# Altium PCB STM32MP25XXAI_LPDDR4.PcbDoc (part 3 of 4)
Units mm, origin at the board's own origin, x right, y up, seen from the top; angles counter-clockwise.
Board outline 172 x 137 mm, 4 copper layers (Top Layer, Signal Layer 1, Signal Layer 2, Bottom Layer), stack 1.614 mm thick; 188 components, 144 nets, 1216 pads, 838 vias.
Unrouted connection lines stored in the file: 13.
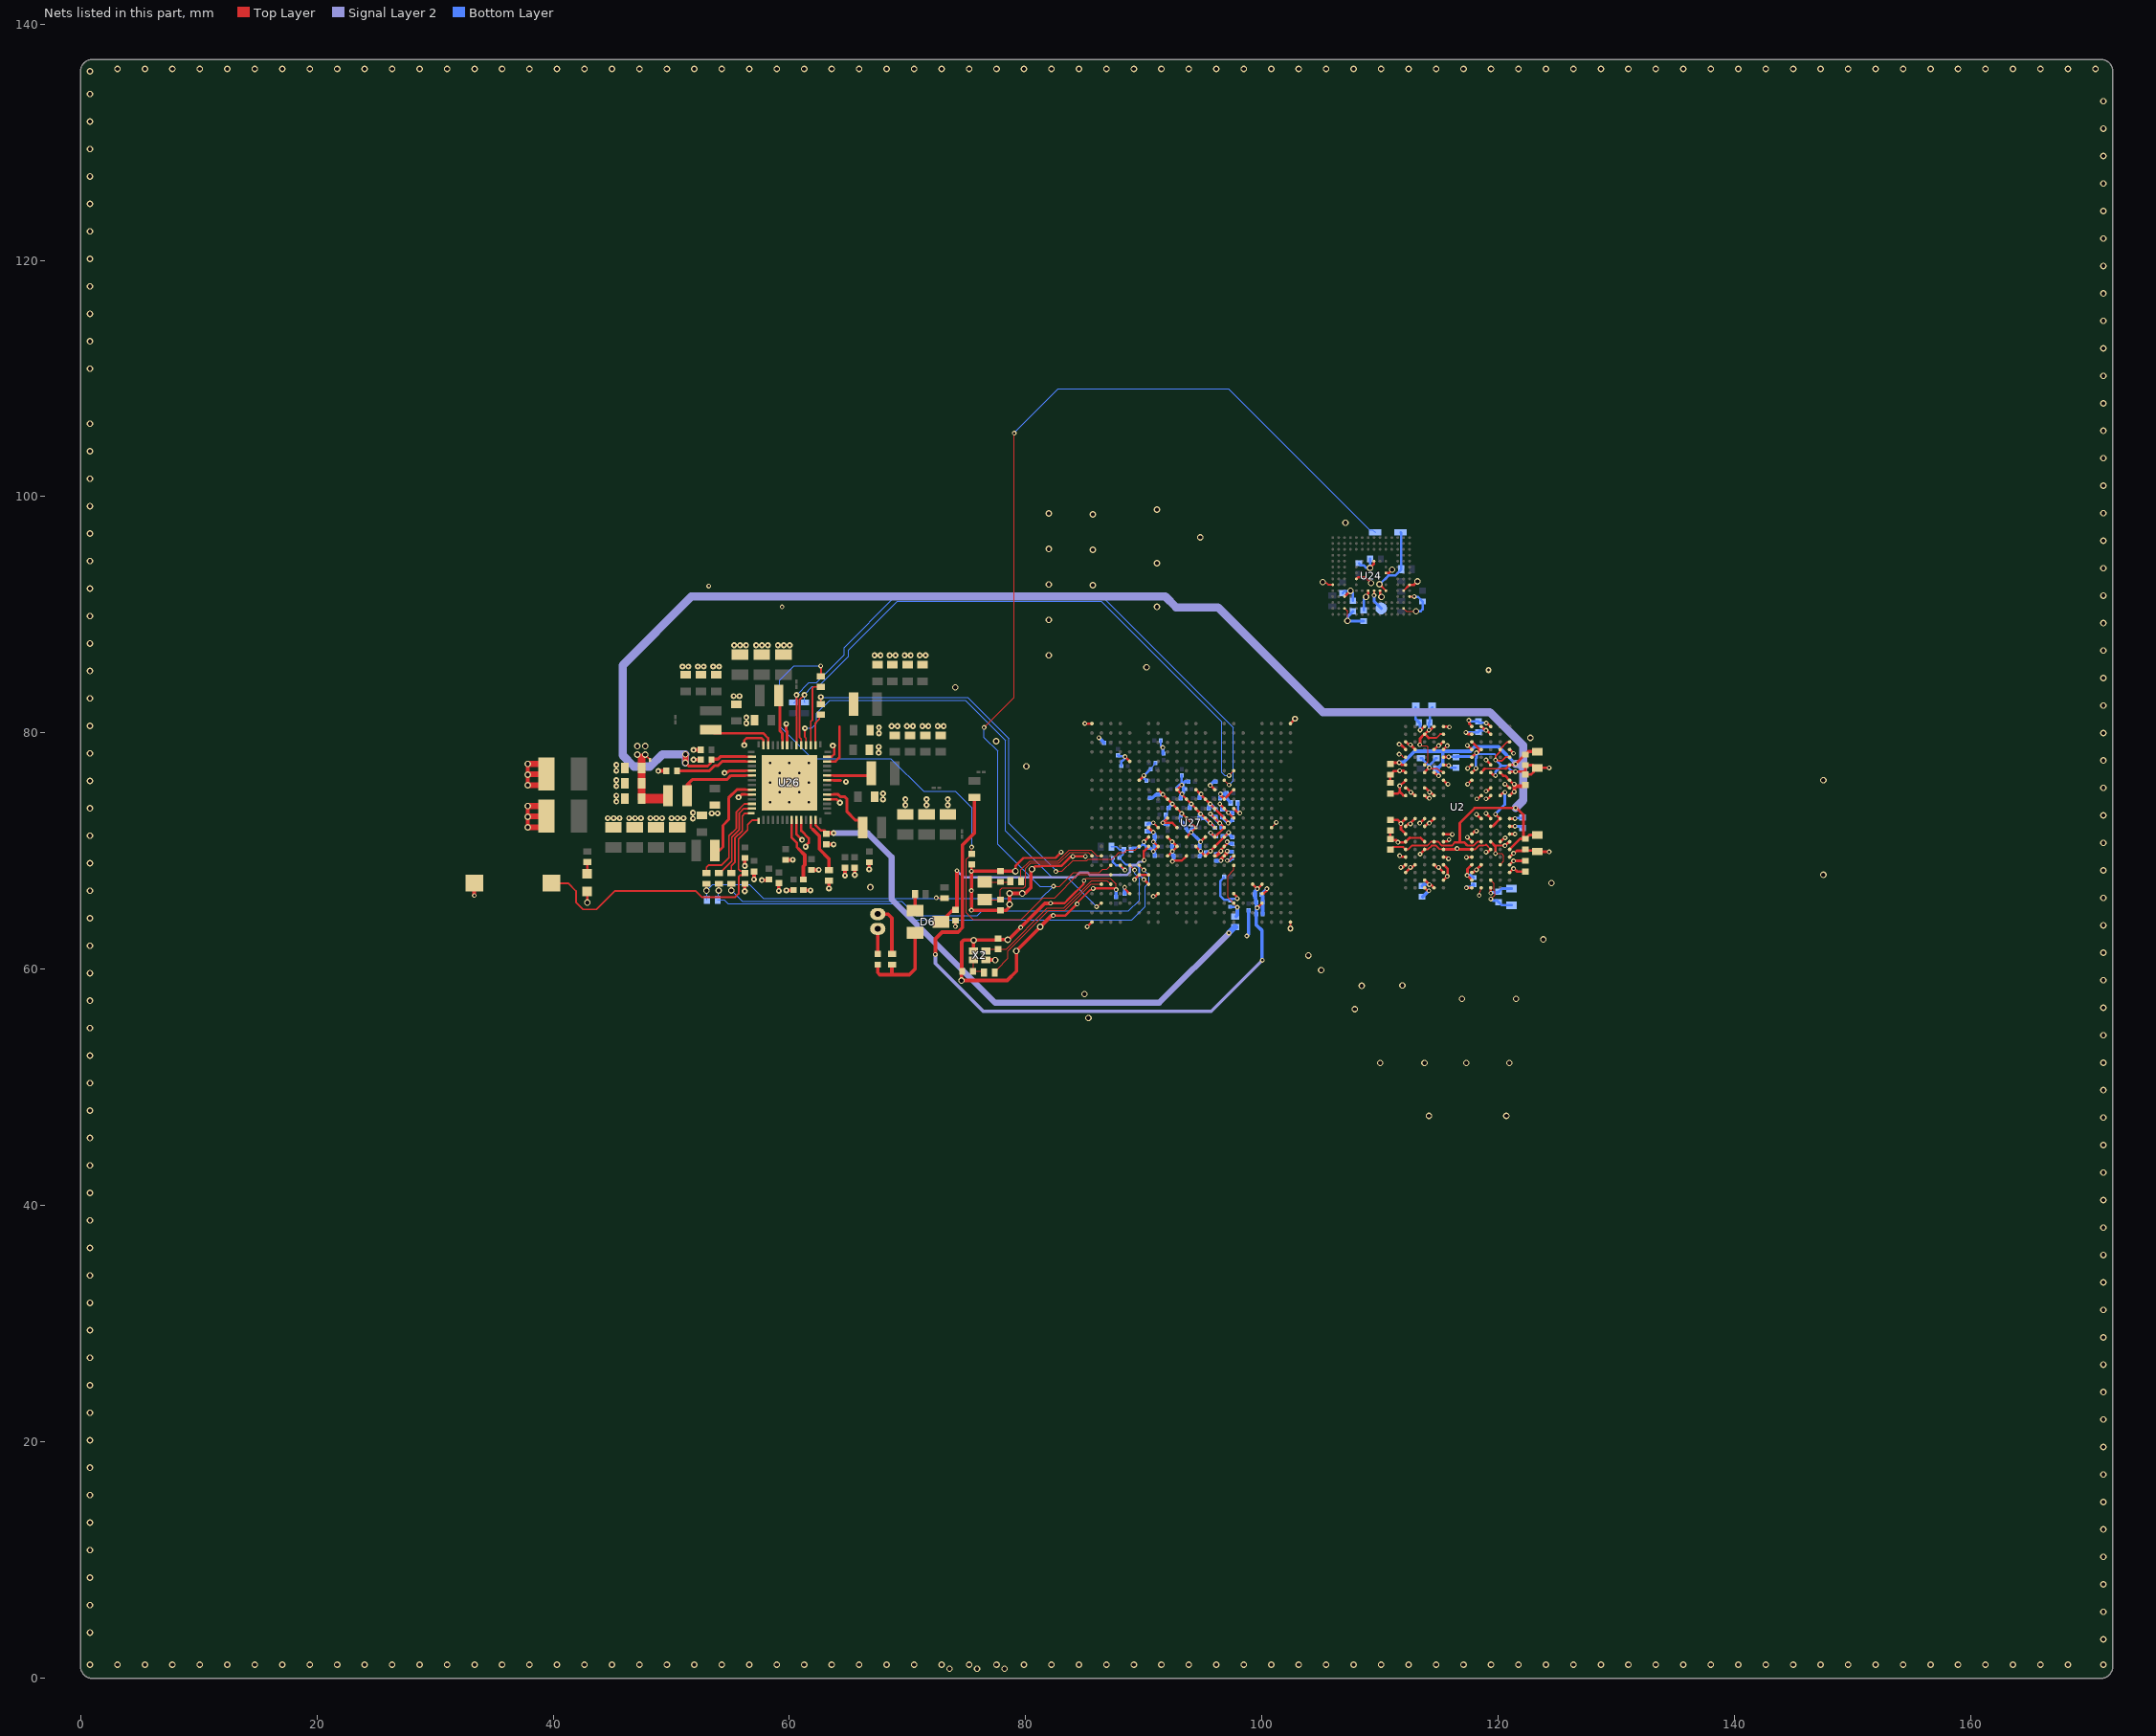
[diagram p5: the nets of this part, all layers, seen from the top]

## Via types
v1: diameter 0.55, hole 0.35, Top Layer to Bottom Layer, 387 vias
v2: diameter 0.4, hole 0.2, Top Layer to Bottom Layer, tented both sides, 173 vias
v3: diameter 0.5, hole 0.2, Top Layer to Bottom Layer, 146 vias
v4: diameter 0.4, hole 0.2, Top Layer to Bottom Layer, 129 vias
v5: diameter 0.5, hole 0.25, Top Layer to Bottom Layer, 3 vias

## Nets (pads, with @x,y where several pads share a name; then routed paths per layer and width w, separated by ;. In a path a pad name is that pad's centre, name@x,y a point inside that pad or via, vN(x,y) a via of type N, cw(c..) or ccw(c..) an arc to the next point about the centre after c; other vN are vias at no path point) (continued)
GND: B2.1 C1.2 C2.1 C3.1 C4.2 C5.1 C6.1 C7.1 C8.1 C9.1 C10.1 C11.2 C12.1 C13.2 C14.1 C15.1 C16.2 C17.1 C18.2 C19.1 C20.1 C21.1 C22.1 C23.1 C24.1 C25.1 C26.1 C27.1 C28.1 C29.1 C30.1 C31.1 C32.1 C33.1 C34.1 C35.1 C36.1 C37.1 C38.1 C39.1 C40.1 C41.1 C42.2 C43.1 C44.2 C45.1 C46.1 C47.2 C50.2 C51.1 C52.1 C53.1 C54.2 C55.1 C56.1 C57.1 C58.1 C59.1 C60.1 C61.1 C62.1 C63.1 C64.1 C65.1 C66.1 C67.1 C68.1 C69.1 C70.1 C71.1 C72.1 C73.1 C74.1 C75.1 C79.1 C81.2 C86.2 C87.1 C89.1 C90.1 C91.2 C92.2 C96.1 C97.1 C98.1 C100.1 C101.1 C102.1 C103.1 C104.1 C105.1 C106.2 C107.2 C108.2 C123.1 C124.2 C125.2 C130.2 C131.1 C141.2 C142.2 C151.2 C152.1 C153.1 C154.1 C155.1 C156.1 C157.1 C175.2 C176.1 C177.1 C178.1 C179.1 C180.1 C181.1 C182.1 C183.1 C184.1 C186.1 C187.1 C188.1 C189.1 C190.2 C193.1 C199.1 C200.1 C202.1 C204.1 C206.1 C207.1 C208.2 C209.1 C212.1 C217.2 C234.1 C275.1 C285.1 LD11.2 R1.1 R57.1 R156.1 U2.A3 U2.A10 U2.AB3 U2.AB5 U2.AB8 U2.AB10 U2.C1 U2.C5 U2.C8 U2.C12 U2.D2 U2.D4 U2.D9 U2.D11 U2.E1 U2.E5 U2.E8 U2.E12 U2.G1 U2.G3 U2.G5 U2.G8 U2.G10 U2.G12 U2.J1 U2.J3 U2.J10 U2.J12 U2.K2 U2.K4 U2.K9 U2.K11 U2.N2 U2.N4 U2.N9 U2.N11 U2.P1 U2.P3 U2.P10 U2.P12 U2.T1 U2.T3 U2.T5 U2.T8 U2.T10 U2.T12 U2.V1 U2.V5 U2.V8 U2.V12 U2.W2 U2.W4 U2.W9 U2.W11 U2.Y1 U2.Y5 U2.Y8 U2.Y12 U24.A6 U24.C4 U24.E7 U24.G5 U24.H10 U24.J5 U24.K8 U24.N2 U24.N5 U24.P4 U24.P6 U26.9 U26.10 U26.18 U26.22 U26.27 U26.36 U26.41 U26.47 U26.52 U26.57 U27.A1 U27.A22 U27.AB1 U27.AB22 U27.E5 U27.G6 U27.H8 U27.H10 U27.H12 U27.H14 U27.H16 U27.J9 U27.J11 U27.J13 U27.J15 U27.K10 U27.K12 U27.K14 U27.L9 U27.L11 U27.L13 U27.L15 U27.M7 U27.M10 U27.M12 U27.M14 U27.M20 U27.N7 U27.N9 U27.N11 U27.N13 U27.N15 U27.P8 U27.P10 U27.P12 U27.P14 U27.R9 U27.R11 U27.R13 U27.R15 U27.T4 U27.U6 U27.U7 U27.W5 U27.W8 U27.W16 U27.W19 X2.2 X2.4 | length 279.9
  Top Layer w0.09: v2(84.925,67.5) 85.12,67.695 87.155,67.695 87.183,67.667 87.65,67.2 v2(87.65,66.75) ; U24.N2@111.98,90.542 112.23,90.292 v1(113.03,90.292) ; U2.T10@113.75,76.65 U2.T10@113.75,76.663 ; v4@114.15,77.063 v4(114.15,77.075) v4@114.228,77.075 ; v4(118.15,73.125) 118.163,73.125 v4@118.175,73.125 ; U2.K4@118.525,72.775 U2.K4@118.55,72.775 ; v4@119.7,69.85 v4(119.75,69.8) 119.755,69.795 120.273,69.795 120.445,69.622 120.445,69.145 U2.D2@120.15,68.85
  Top Layer w0.1: v3@44.624,72.799 v3@44.625,72.8 ; X2.2@75.547,61.575 X2.2@75.548,61.576 ; v1@75.573,62.448 v1(75.587,62.462) v1@75.6,62.475 ; U27.M20@100.8,72 101.2,72.4 v4(101.2,72.425) ; v4(111.6,78.2) 111.658,78.143 111.764,78.143 111.941,77.965 112.135,77.965 U2.V12@112.15,77.95
  Top Layer w0.15: v2(84.345,65.531) 84.345,65.598 84.448,65.702 84.448,65.708 85.465,66.725 85.523,66.725 85.636,66.838 v2(85.703,66.838) ; v1(105.13,92.762) 105.201,92.692 105.466,92.692 105.611,92.547 105.975,92.547 U24.A6@105.98,92.542 ; U24.P4@112.48,91.542 v2(112.88,91.542) ; 112.5,71.125 113.413,71.125 ; v4@114.228,77.075 114.228,77.065 114.318,76.975 114.832,76.975 115.037,76.77 115.19,76.77 115.31,76.65 U2.T8@115.35,76.65 ; 119.7,70.475 v4(120.55,70.475) ; U2.Y1@120.899,79.272 120.853,79.226 120.724,79.226 120.15,78.652 U2.W2@120.15,78.6 120.15,78.43 119.786,78.065 119.786,77.754 119.741,77.709 119.773,77.677 119.978,77.677 120.02,77.635 120.29,77.635 120.611,77.957 120.944,77.957 U2.V1@120.95,77.95
  Top Layer w0.2: v1(42.887,65.648) LD11.2@42.887,66.577 ; U26.27@63.17,78 63.579,78 63.77,78.191 63.77,78.91 v3@63.816,78.956 ; v3(63.67,78.93) v3@63.727,78.873 ; C87.1@74.05,64.125 74.05,63.634 v2(74.051,63.633) ; v2(75.402,68.305) 75.416,68.319 C33.1@75.416,68.915 ; v1(79.125,68.3) 79.125,68.75 79.8,69.425 82.507,69.425 v2(83.002,69.92) ; v1(80.525,68.475) 80.568,68.475 80.818,68.725 81.262,68.725 81.287,68.75 83.012,68.75 83.784,69.522 83.94,69.522 v2(83.978,69.56) v2(85.046,69.56) ; v2(82.1,65.6) 83.28,65.6 83.703,66.023 84.887,67.207 84.887,67.462 v2(84.925,67.5) ; v2(82.325,64.55) 83.364,64.55 v2(84.345,65.531) ; v2(85,80.805) 85.005,80.8 U27.A1@85.6,80.8 ; v2(85.2,63.6) U27.AB1@85.6,64 ; v2(85.703,66.838) 87.508,66.838 87.596,66.75 v2(87.65,66.75) ; U27.T4@88,68.8 v2(88.4,68.4) ; v2(88.37,66.944) 88.408,66.905 88.408,66.792 U27.W5@88.8,66.4 ; v2(88.4,78) U27.E5@88.8,77.6 ; v2(89.2,67.6) U27.U6@89.6,68 U27.U7@90.4,68 ; U27.G6@89.6,76 v2(90,76.4) ; v2(90,70.8) U27.N7@90.4,71.2 ; v2(90.788,66.173) 90.827,66.211 90.984,66.211 91.173,66.4 U27.W8@91.2,66.4 ; v2@90.8,70 U27.P8@91.2,70.4 v2(90.8,70.8) ; U27.H8@91.2,75.2 v2(91.6,74.8) U27.J9@92,74.4 v2(92.4,74) v2@93.225,73.175 ; U27.R9@92,69.6 92.025,69.6 v2(92.4,69.975) 92.8,70.375 U27.P10@92.8,70.4 92.4,70.8 U27.N9@92,71.2 ; U27.L9@92,72.8 v2(91.6,72.4) 92.4,72.4 U27.M10@92.8,72 ; v2@92.454,69.1 92.4,69.1 92.5,69.2 93.2,69.2 U27.R11@93.6,69.6 ; v2(93.2,73.175) v2@93.225,73.175 ; v2(93.201,75.6) 92.801,75.2 v2@93.226,74.775 ; v2(93.226,74.85) v2@93.226,74.775 ; U27.N11@93.6,71.2 v2(94,71.6) U27.M12@94.4,72 v2@93.225,73.175 ; U27.P12@94.4,70.4 v2(94.8,70) U27.R13@95.2,69.6 95.787,70.188 ; U27.H12@94.407,75.2 94.757,74.85 v2(94.832,74.85) 94.832,74.775 v2(95.607,74) U27.L15@96.807,72.8 ; v2(94.8,70.8) U27.N13@95.2,71.2 ; v2@95.625,75.575 U27.H14@96,75.2 ; U27.P14@96,70.4 95.787,70.188 ; U27.M14@96,72 95.626,72.375 94.851,73.15 v2(94.801,73.15) 94.801,73.2 v2(94.001,74) v2@93.226,74.775 ; v2(96.475,74.85) 96.514,74.812 96.514,74.686 U27.J15@96.8,74.4 U27.H16@97.6,75.2 ; U27.L15@96.8,72.8 97.087,72.513 97.087,72.413 v2(97.125,72.375) ; v2(97.175,71.575) 95.787,70.188 ; U27.W16@97.6,66.4 97.862,66.138 97.862,66.038 v2(97.9,66) ; U27.W19@100,66.4 100.019,66.419 100.144,66.419 v4@100.4,66.675 ; v5(102.4,63.45) U27.AB22@102.4,64 ; U27.A22@102.41,80.8 102.41,80.811 102.76,81.161 v5@102.76,81.175 ; U24.C4@106.98,91.542 107.43,91.992 107.44,91.992 v1(107.48,92.032) ; U24.E7@107.98,93.042 108.13,93.192 108.725,93.192 v1(109.23,92.687) ; v1(108.805,91.517) 108.805,91.605 108.98,91.78 U24.G5@108.98,92.042 ; v1(109.13,93.967) 109.48,94.317 U24.H10@109.48,94.542 ; U24.J5@109.98,92.042 109.98,91.737 110.105,91.612 v1(110.105,91.517) ; U24.K8@110.48,93.542 110.73,93.542 v1(111.005,93.817) ; U24.N5@111.98,92.042 U24.P6@112.48,92.542 112.86,92.542 v1(113.155,92.837)
  Top Layer w0.21: v3(56.175,78.975) 56.175,79.375 56.38,79.58 57.609,79.58 57.8,79.389 U26.41@57.8,78.97 ; 56.275,74.8 U26.52@56.83,74.8 ; 56.275,76.8 U26.47@56.83,76.8 ; U26.36@59.8,78.97 59.8,79.525 ; U26.9@60.6,72.63 60.6,71.42 v3(61.068,70.952) ; U26.10@61,72.63 61,71.734 61.635,71.099 61.635,70.72 61.37,70.456 v3(61.37,70.377) ; U26.18@63.17,74.4 63.972,74.4 v3(64.272,74.1) ; U26.22@63.17,76 63.725,76
  Top Layer w0.22: C50.2@110.85,71.75 C102.1@110.85,71.025 110.931,70.944 111.331,70.944 111.526,70.75 v2@111.55,70.75 ; C105.1@110.85,75.775 C101.1@110.85,76.475 110.875,76.475 111.02,76.62 111.02,76.637 111.149,76.766 v4@111.65,76.766 ; v2@111.55,70.747 112.076,70.747 112.129,70.8 U2.G12@112.15,70.8 112.172,70.8 112.497,71.125 112.5,71.125 ; v4(111.65,69.625) 111.699,69.625 111.809,69.515 112.135,69.515 U2.E12@112.15,69.5 ; v4(111.65,76.8) 111.661,76.79 111.989,76.79 112.129,76.65 U2.T12@112.15,76.65 ; U2.C12@112.15,68.2 112.172,68.2 112.497,68.525 112.525,68.525 112.56,68.559 112.638,68.559 112.929,68.85 U2.D11@112.95,68.85 ; U2.J12@112.15,72.1 112.172,72.1 112.413,72.341 112.516,72.341 112.55,72.375 112.563,72.375 112.938,72.75 U2.K11@112.95,72.75 ; U2.P12@112.15,75.35 112.166,75.335 112.244,75.335 112.579,75 v4@112.6,75 ; U2.Y12@112.15,79.25 112.172,79.25 112.388,79.034 112.516,79.034 v4(112.55,79) U2.W11@112.95,78.6 ; v4@112.585,74.991 112.638,74.991 112.929,74.7 U2.N11@112.95,74.7 ; v4(113.375,80.25) 113.424,80.25 113.509,80.334 113.513,80.334 113.729,80.55 U2.AB10@113.75,80.55 ; 113.413,71.125 113.738,70.8 U2.G10@113.75,70.8 ; U2.A10@113.75,66.9 113.772,66.9 113.988,66.684 114.091,66.684 v4(114.125,66.65) ; U2.J10@113.75,72.1 113.772,72.1 114.013,72.341 114.116,72.341 v4(114.15,72.375) 114.163,72.375 114.538,72.75 U2.K9@114.55,72.75 ; U2.P10@113.75,75.35 113.766,75.335 113.849,75.335 114.133,75.05 114.175,75.05 114.188,75.05 114.538,74.7 U2.N9@114.55,74.7 ; U2.T10@113.75,76.663 v4@114.15,77.063 ; U2.D9@114.55,68.85 114.572,68.85 114.763,68.659 114.916,68.659 v4(114.95,68.625) 114.95,68.613 115.35,68.213 U2.C8@115.35,68.2 ; U2.W9@114.55,78.6 114.572,78.6 114.863,78.891 114.916,78.891 v4(114.95,78.925) 114.985,78.959 115.038,78.959 115.329,79.25 U2.Y8@115.35,79.25 ; U2.E8@115.35,69.5 115.366,69.485 115.592,69.485 115.727,69.35 v4(115.775,69.35) ; U2.G8@115.35,70.8 115.366,70.815 115.692,70.815 115.777,70.9 v4@115.825,70.9 ; U2.V8@115.35,77.95 115.363,77.963 115.788,77.963 v4(115.8,77.975) ; U2.AB8@115.35,80.55 115.366,80.535 115.767,80.535 115.802,80.5 v4(115.85,80.5) ; v4(117.3,69.475) 117.313,69.488 117.738,69.488 U2.E5@117.75,69.5 ; v4(117.375,71.175) U2.G5@117.738,70.813 ; v4(117.5,81.075) 117.535,81.041 117.535,80.787 117.75,80.572 U2.AB5@117.75,80.55 ; U2.C5@117.75,68.2 117.877,68.2 118.102,68.425 v4(118.15,68.425) 118.15,68.438 118.55,68.838 U2.D4@118.55,68.85 ; U2.T5@117.75,76.65 v4(118.1,77) ; U2.V5@117.75,77.95 117.763,77.95 118.138,78.325 v4(118.15,78.325) 118.185,78.359 118.288,78.359 U2.W4@118.529,78.6 ; U2.Y5@117.75,79.25 118.385,78.615 118.513,78.615 U2.W4@118.529,78.6 ; v4@118.163,73.125 118.538,72.75 U2.K4@118.55,72.75 ; v4(118.175,74.425) 118.21,74.459 118.288,74.459 118.529,74.7 U2.N4@118.55,74.7 ; U2.W4@118.55,78.6 U2.W4@118.529,78.6 ; v4(118.95,75.075) 118.999,75.075 119.089,75.165 119.128,75.165 119.273,75.31 119.289,75.31 119.329,75.35 U2.P3@119.35,75.35 ; v4(118.97,80.845) 118.97,80.84 118.98,80.83 118.95,80.8 118.985,80.766 119.113,80.766 119.329,80.55 U2.AB3@119.35,80.55 ; v4(119.35,66.45) U2.A3@119.35,66.9 ; U2.G3@119.35,70.8 119.75,70.4 v4(119.75,69.8) ; U2.J3@119.35,72.1 119.366,72.115 119.516,72.115 U2.K2@120.15,72.75 120.138,72.75 119.763,73.125 v4(119.75,73.125) ; U2.T3@119.35,76.65 119.566,76.434 v4@119.716,76.434 ; U2.N2@120.15,74.7 120.391,74.941 120.516,74.941 v4(120.55,74.975) ; v4(120.55,70.475) 120.585,70.509 120.638,70.509 120.929,70.8 U2.G1@120.95,70.8 ; v4(120.55,75.675) 120.625,75.675 U2.P1@120.95,75.35 ; U2.C1@120.95,68.2 v4(121.275,68.525) 121.324,68.525 121.574,68.275 C106.2@122.25,68.275 ; U2.E1@120.95,69.5 120.963,69.5 121.263,69.8 121.324,69.8 121.549,70.025 C103.1@122.25,70.025 ; U2.J1@120.95,72.1 v4(121.4,72.1) ; U2.T1@120.95,76.65 120.972,76.65 121.047,76.725 v4(121.45,76.725) C107.2@122.275,76.725 ; C103.1@122.25,70.15 122.338,70.063 123.188,70.063 C51.1@123.275,69.975 ; C51.1@123.3,69.975 123.325,69.95 v4(124.3,69.95) ; C100.1@123.3,77.025 C100.1@123.175,77.025 ; v4(124.3,77.05) 123.2,77.05 C100.1@123.175,77.025 ; C107.2@122.275,76.725 C104.1@122.275,77.275 122.925,77.275 C100.1@123.175,77.025 ; C107.2@122.275,76.725 C107.2@122.275,76.5 122.775,76.5 122.965,76.69 122.965,76.815 C100.1@123.175,77.025
  Top Layer w0.25: v3(54.508,76.625) 54.556,76.673 54.757,76.673 54.884,76.8 56.275,76.8 ; v3(55.687,74.563) 55.721,74.563 55.959,74.8 56.275,74.8 ; v3(59.725,80.775) 59.725,80.214 59.8,80.139 59.8,79.525 ; 63.725,76 64.33,76 ; v3@64.257,74.1 v3(64.272,74.1)
  Top Layer w0.3: v2(33.319,66.245) 33.324,66.25 33.324,67.279 B2.1@33.34,67.295 ; v1(37.848,72.014) v1(37.848,72.914) v1(37.848,73.814) ; v1(37.848,75.576) v1(37.848,76.476) v1(37.848,77.376) ; v3(48.895,76.79) C43.1@49.555,76.79 ; v3(51.885,77.75) C40.1@52.495,77.75 ; v3(51.885,78.575) C39.1@52.495,78.575 ; v3@56.225,68.81 C217.2@56.225,69.42 ; v3@56.227,66.58 C155.1@56.227,67.185 ; v3(57,67.61) C154.1@57,68.215 ; v3(57.665,67.55) C142.2@58.275,67.55 ; v3@59.1,66.69 C141.2@59.1,67.3 ; C153.1@59.675,69.27 v3(60.285,69.27) ; v3(59.74,66.68) C91.2@60.35,66.68 ; C208.2@61.175,66.68 v3(61.785,66.68) ; C209.1@61.85,68.42 v3(62.485,68.42) ; C156.1@63.125,70.57 v3(63.735,70.57) ; v3(63.35,66.84) R57.1@63.35,67.5 ; v3(64.7,67.93) C189.1@64.7,68.59 ; v3(65.525,67.99) C188.1@65.525,68.59 C188.1@65.525,68.65 ; v3@66.75,68.465 66.747,68.467 66.747,69.063 C190.2@66.75,69.065 ; C92.2@74.563,59.875 74.563,59.087 74.588,59.063 78.438,59.063 79.225,59.85 79.225,61.525 v1(79.2,61.55) 81.225,63.575 v1(81.225,63.6) 82.156,64.531 82.306,64.531 v2(82.325,64.55) ; C92.2@74.625,59.825 74.576,59.874 74.576,62.299 74.752,62.475 75.6,62.475 76,62.475 76.013,62.488 76.663,62.488 76.675,62.475 77.5,62.475 77.625,62.6 C90.1@77.65,62.6 77.736,62.514 v1@78.475,62.514 ; v2(75.4,65) C86.2@77.85,65 ; 75.4,65.275 v2@75.4,66.65 ; v2@75.4,68.3 v2@75.402,68.3 ; v2(75.402,66.655) v2@75.402,68.3 ; v2(75.402,68.305) v2@75.402,68.3 ; X2.2@75.573,61.551 v1@75.573,62.448 ; X2.4@76.66,60.788 76.667,60.794 77.408,60.794 v1(77.415,60.788) ; C86.2@77.955,65.105 C86.2@77.85,65 ; v1(78.475,62.5) 78.525,62.5 v2(79.575,63.55) 81.606,65.581 v2@82.081,65.581 ; v1(79.125,68.3) C81.2@77.85,68.3 v2@75.402,68.3 ; v1(80.525,68.475) 80.43,68.38 80.43,66.905 79.993,66.468 79.748,66.468 v1(79.7,66.42) 79.695,66.425 v1(78.625,66.425) v1(78.625,65.5) 78.578,65.452 78.578,65.239 78.339,65 C86.2@77.85,65 ; U27.M7@90.4,72 v2(90.8,71.6) ; v2(96.525,69.2) 96.544,69.219 96.544,69.344 U27.R15@96.8,69.6 96.975,69.775 96.975,69.898 97.05,69.973 v2(97.05,70)
  Top Layer w0.5: v1(37.848,72.014) 39.39,72.014 C18.2@39.437,72.061 ; v1(37.848,72.914) 37.862,72.914 37.909,72.961 C18.2@39.437,72.961 ; v1(37.848,73.814) C18.2@39.379,73.814 ; v1(37.848,75.576) 39.39,75.576 C42.2@39.437,75.623 ; v1(37.848,76.476) 37.862,76.476 37.909,76.523 C42.2@39.437,76.523 ; v1(37.848,77.376) C42.2@39.379,77.376
  Bottom Layer w0.1: C73.1@90.575,76.925 90.7,77.05 90.7,77.13 90.85,77.28 90.85,77.35 C66.1@90.9,77.4 ; C212.1@91.86,73.1 92.032,73.272 92.032,73.582 C3.1@92.1,73.65 ; C10.1@92.35,70.327 C10.1@92.35,70.45
  Bottom Layer w0.15: v4@118.15,78.35 118.191,78.35 118.341,78.2 119.684,78.2 119.75,78.134 v4@119.75,77.75
  Bottom Layer w0.2: C75.1@87.375,69.425 87.375,69.075 87.65,68.8 87.9,68.8 88.3,68.4 v2(88.4,68.4) ; C70.1@87.8,78.1 87.862,78.038 88.362,78.038 v2(88.4,78) 88.405,77.996 88.405,77.854 88.205,77.655 88.18,77.655 88.163,77.655 88.075,77.567 C275.1@88.075,77.2 ; C79.1@88.9,70.125 89.075,70.3 89.625,70.3 89.962,70.636 89.962,70.761 v2(90,70.8) 90.038,70.761 90.038,70.522 C234.1@90.275,70.285 ; v2@89.988,76.388 90.038,76.338 90.038,76.137 C69.1@90.205,75.97 ; v2(90,76.4) 90.525,76.925 C73.1@90.575,76.925 ; C66.1@90.9,77.4 C66.1@90.975,77.475 ; C97.1@91.425,79.375 91.425,78.955 91.6,78.781 v2(91.6,78.775) ; v2(93.201,75.6) C71.1@93.201,76.4 ; C11.2@95.25,69.9 95.312,69.962 95.587,69.962 v2(95.625,70) ; C89.1@96.75,67.8 96.75,67.75 96.45,67.45 96.45,66.225 96.775,65.9 97.3,65.9 97.35,65.95 97.444,65.95 97.456,65.962 97.721,65.962 97.862,65.962 v2(97.9,66) ; C178.1@106.835,91.855 107,92.02 107.5,92.02 107.685,91.835 C182.1@107.685,91.18 ; C177.1@108.19,94.355 108.345,94.2 108.583,94.2 108.783,94.001 109.104,94.001 109.15,93.955 C180.1@109.15,94.739 ; C181.1@108.602,90.38 108.602,91.282 v1@108.825,91.505 ; v2@112.9,91.53 113.19,91.53 C179.1@113.59,91.13 113.59,90.467 113.433,90.31 113.08,90.31 v1@113.05,90.28
  Bottom Layer w0.22: C123.1@113,82.125 113,81.2 ; C123.1@113,82.15 113,81.2 ; C125.2@113.275,80.875 C125.2@113.316,80.834 ; v4(113.375,80.25) C125.2@113.375,80.775 ; v4@113.375,80.275 C125.2@113.375,80.775 ; R156.1@113.425,77.875 113.52,77.875 113.665,77.73 113.665,77.685 114.116,77.234 114.116,77.134 114.15,77.1 114.185,77.134 114.185,77.262 114.185,77.274 114.58,77.67 114.58,77.73 114.725,77.875 C131.1@114.75,77.875 ; C175.2@113.55,66.15 C175.2@113.6,66.15 ; v4@115.8,78 116.35,78 C130.2@116.4,77.95 116.46,78.01 117.86,78.01 117.86,78.035 v4(118.15,78.325) ; v4(117.5,81.075) 117.6,80.975 C124.2@118.3,80.975 118.416,80.859 118.916,80.859 v4@118.95,80.825 ; v4@118.1,77.025 118.1,77.833 118.155,77.888 118.155,78.345 v4@118.15,78.35 ; v4@119.35,66.475 119.385,66.509 119.96,66.509 C108.2@120.025,66.575 120.05,66.575 120.3,66.825 C176.1@121.125,66.825 ; v4@119.75,73.15 120.55,73.95 v4(120.55,74.975) ; v4@119.75,76.425 119.75,76.7 120.275,77.225 ; v4@119.75,77.75 120.275,77.225 ; v4@121.352,72.125 121.4,72.125 121.435,72.091 121.91,72.091 C151.2@122.05,71.95 ; v4@121.45,76.75 121.416,76.784 121.111,76.784 120.67,77.225 120.275,77.225 ; 113,81.2 113.316,80.884 C125.2@113.316,80.859 ; 113,81.2 113,81.175 C125.2@113.275,80.9 C125.2@113.316,80.859 ; C125.2@113.316,80.834 C125.2@113.375,80.775 ; C125.2@113.316,80.834 C125.2@113.316,80.859 ; C125.2@113.316,80.859 113.375,80.8 C125.2@113.375,80.775
  Bottom Layer w0.3: v2(86.194,79.6) 86.2,79.6 C98.1@86.625,79.175 ; C67.1@87.65,66.095 v2(87.65,66.75) ; v2(88.37,66.944) 88.375,66.938 C68.1@88.375,66.4 ; C234.1@90.275,70.285 90.3,70.26 90.549,70.26 90.781,70.028 90.781,69.994 v2(90.8,69.975) ; C61.1@90.317,71.688 90.367,71.638 90.735,71.638 90.773,71.6 v2(90.8,71.6) 90.8,71.573 90.9,71.473 90.9,71.225 C52.1@90.925,71.2 90.925,70.925 v2(90.8,70.8) 90.925,70.675 C47.2@90.925,70.388 90.925,70.1 v2(90.8,69.975) ; C74.1@90.5,74.5 90.725,74.5 91.025,74.8 C6.1@91.2,74.8 v2(91.6,74.8) ; C44.2@90.925,69.6 90.925,69.85 v2(90.8,69.975) ; C72.1@91.6,78.25 v2@91.6,78.775 ; 91.86,72.925 91.86,72.687 91.6,72.427 v2(91.6,72.4) 91.725,72.275 C46.1@92.025,72.275 ; C3.1@92.1,73.65 92.1,73.7 v2(92.4,74) ; C10.1@92.35,70.327 92.381,70.296 92.381,70.021 92.4,70.002 v2(92.4,69.975) ; C10.1@92.35,70.45 92.375,70.475 92.375,70.748 92.4,70.773 v2@92.4,70.8 ; v2@92.4,69.948 92.425,69.923 92.425,69.605 C45.1@92.475,69.555 ; v2@92.525,69.216 C45.1@92.525,69.6 ; C4.2@92.825,75.25 92.825,75.4 93.025,75.6 v2(93.201,75.6) ; C5.1@93.101,74.475 93.101,74.725 93.351,74.975 93.351,75.45 v2(93.201,75.6) ; v2(93.2,73.175) 93.175,73.175 93.1,73.1 C1.2@93.1,72.825 93.1,72.55 93.225,72.425 93.304,72.425 93.45,72.279 93.45,72.2 93.575,72.075 C9.1@93.575,72 ; 93.65,71.775 93.825,71.6 v2(94,71.6) ; C17.1@93.775,75.875 93.476,75.875 v2(93.201,75.6) ; C2.1@93.876,73.65 93.876,73.875 v2(94.001,74) ; C7.1@94.125,72 94,71.875 v2(94,71.6) ; C31.1@94.675,72.775 95.201,72.775 v2(95.601,72.375) 95.625,72.375 C57.1@96.026,71.974 ; C31.1@94.676,72.825 94.676,73.075 94.751,73.15 v2(94.801,73.15) ; C14.1@94.7,74.48 94.7,74.718 v2(94.832,74.85) ; C12.1@94.75,69.575 94.8,69.625 v2(94.8,70) 94.725,70.075 94.725,70.725 v2(94.8,70.8) v2(94,71.6) ; C13.2@95.507,73.625 95.507,73.9 v2(95.607,74) ; v2@95.607,73.999 C60.1@96.081,73.524 ; v2@95.607,75.6 95.607,75.575 95.907,75.875 C16.2@96.075,75.875 ; C59.1@96.1,69.175 96.113,69.187 96.513,69.187 v2(96.525,69.2) ; C15.1@96.438,74.513 96.475,74.55 v2(96.475,74.85) 96.9,74.85 96.95,74.9 96.95,74.523 R1.1@97.324,74.149 ; C56.1@96.649,72.831 96.649,72.849 96.624,72.874 96.632,72.875 96.925,72.582 96.925,72.575 v2(97.125,72.375) 97.145,72.394 97.245,72.394 C58.1@97.5,72.65 ; C55.1@96.65,71.275 96.875,71.275 v2(97.175,71.575) 97.194,71.556 97.194,71.456 C54.2@97.475,71.175 ; v2(97.05,70) v2@97.05,70.036 ; v2@97.2,70 97.25,69.95 C53.1@97.45,69.95 ; v2(98.7,62.825) 98.7,62.835 98.85,62.985 C96.1@98.85,65 ; C63.1@100.05,64.675 C64.1@100.05,65.675 100.05,66.2 C65.1@99.925,66.325 100.399,66.798 v4(100.399,66.828) ; v1@107.075,97.775 v1@107.085,97.785 ; C175.2@113.6,66.15 v4@114.125,66.675
  other v1: 73.55,0.8 75.875,0.8 78.2,0.8 0.8,1.15 3.125,1.15 5.45,1.15 7.775,1.15 10.1,1.15 12.425,1.15 14.75,1.15 17.075,1.15 19.4,1.15 21.725,1.15 24.05,1.15 26.375,1.15 28.7,1.15 31.025,1.15 33.35,1.15 35.675,1.15 38,1.15 40.325,1.15 42.65,1.15 44.975,1.15 47.3,1.15 49.625,1.15 51.95,1.15 54.275,1.15 56.6,1.15 58.925,1.15 61.25,1.15 63.575,1.15 65.9,1.15 68.225,1.15 70.55,1.15 72.875,1.15 75.2,1.15 77.525,1.15 79.85,1.15 82.175,1.15 84.5,1.15 86.825,1.15 89.15,1.15 91.475,1.15 93.8,1.15 96.125,1.15 98.45,1.15 100.775,1.15 103.1,1.15 105.425,1.15 107.75,1.15 110.075,1.15 112.4,1.15 114.725,1.15 117.05,1.15 119.375,1.15 121.7,1.15 124.025,1.15 126.35,1.15 128.675,1.15 131,1.15 133.325,1.15 135.65,1.15 137.975,1.15 140.3,1.15 142.625,1.15 144.95,1.15 147.275,1.15 149.6,1.15 151.925,1.15 154.25,1.15 156.575,1.15 158.9,1.15 161.225,1.15 163.55,1.15 165.875,1.15 168.2,1.15 171.2,1.15 171.2,3.3 0.8,3.875 171.2,5.625 0.8,6.2 171.2,7.95 0.8,8.525 171.2,10.275 0.8,10.85 171.2,12.6 0.8,13.175 171.2,14.925 0.8,15.5 171.2,17.25 0.8,17.825 171.2,19.575 0.8,20.15 171.2,21.9 0.8,22.475 171.2,24.225 0.8,24.8 171.2,26.55 0.8,27.125 171.2,28.85 0.8,29.45 171.2,31.175 0.8,31.775 171.2,33.5 0.8,34.1 171.2,35.825 0.8,36.425 171.2,38.15 0.8,38.75 171.2,40.475 0.8,41.075 171.2,42.8 0.8,43.4 171.2,45.125 0.8,45.725 171.2,47.45 114.125,47.6 120.675,47.6 0.8,48.05 171.2,49.775 0.8,50.375 110,52.075 113.75,52.075 117.275,52.075 120.925,52.075 171.2,52.1 0.8,52.7 171.2,54.425 0.8,55.025 85.3,55.875 107.85,56.625 171.2,56.75 0.8,57.35 116.925,57.5 121.5,57.5 84.975,57.9 108.427,58.602 111.875,58.625 74.563,59.05 171.2,59.075 0.8,59.675 105,59.925 103.925,61.175 171.2,61.4 0.8,62 123.806,62.533 171.2,63.725 0.8,64.325 171.2,66.05 0.8,66.65 66.85,66.945 124.495,67.301 147.5,68 171.2,68.375 0.8,68.975 171.2,70.7 0.8,71.3 171.2,73.025 0.8,73.625 171.2,75.35 0.8,75.95 147.5,76 80.05,77.175 171.2,77.675 0.8,78.275 77.495,79.305 122.714,79.595 171.2,80 0.8,80.6 171.2,82.325 0.8,82.925 74.035,83.865 171.2,84.65 0.8,85.25 90.219,85.569 81.95,86.575 171.2,86.975 0.8,87.575 171.2,89.3 81.95,89.575 0.8,89.9 91.1,90.675 171.2,91.625 0.8,92.225 85.675,92.5 81.95,92.575 171.2,93.95 91.1,94.375 0.8,94.55 85.675,95.5 81.95,95.575 171.2,96.275 94.775,96.55 0.8,96.875 107.055,97.787 85.675,98.5 81.95,98.575 171.2,98.6 91.1,98.9 0.8,99.2 171.2,100.925 0.8,101.525 171.2,103.25 0.8,103.85 171.2,105.575 0.8,106.175 171.2,107.9 171.2,110.225 0.8,110.825 171.2,112.55 0.8,113.15 171.2,114.875 0.8,115.475 171.2,117.2 0.8,117.8 171.2,119.525 0.8,120.125 171.2,121.85 0.8,122.45 171.2,124.175 0.8,124.775 171.2,126.5 0.8,127.1 171.2,128.825 0.8,129.425 171.2,131.15 0.8,131.75 171.2,133.475 0.8,134.075 0.8,136 3.125,136.2 5.45,136.2 7.775,136.2 10.1,136.2 12.425,136.2 14.75,136.2 17.075,136.2 19.4,136.2 21.725,136.2 24.05,136.2 26.375,136.2 28.7,136.2 31.025,136.2 33.35,136.2 35.675,136.2 38,136.2 40.325,136.2 42.65,136.2 44.975,136.2 47.3,136.2 49.625,136.2 51.95,136.2 54.275,136.2 56.6,136.2 58.925,136.2 61.25,136.2 63.575,136.2 65.9,136.2 68.225,136.2 70.55,136.2 72.875,136.2 75.2,136.2 77.525,136.2 79.85,136.2 82.175,136.2 84.5,136.2 86.825,136.2 89.15,136.2 91.475,136.2 93.8,136.2 96.125,136.2 98.45,136.2 100.775,136.2 103.1,136.2 105.425,136.2 107.75,136.2 110.075,136.2 112.4,136.2 114.725,136.2 117.05,136.2 119.375,136.2 121.7,136.2 124.025,136.2 126.35,136.2 128.675,136.2 131,136.2 133.325,136.2 135.65,136.2 137.975,136.2 140.3,136.2 142.625,136.2 144.95,136.2 147.275,136.2 149.6,136.2 151.925,136.2 154.25,136.2 156.575,136.2 158.9,136.2 161.225,136.2 163.55,136.2 165.875,136.2 168.2,136.2 170.525,136.2
  other v2: 92.4,69.125 111.5,70.755 92.39,70.8 95.6,75.575 59.375,90.675 53.175,92.437
  other v3: 56.222,66.61 59.1,66.64 66.745,68.46 56.225,68.76 51.825,72.75 44.624,72.798 45.125,72.798 45.626,72.798 46.424,72.798 46.925,72.798 47.426,72.798 48.224,72.798 48.725,72.798 49.226,72.798 50.024,72.798 50.525,72.798 51.026,72.798 53.424,73.202 53.925,73.202 51.825,73.25 69.804,73.9 71.604,73.9 73.404,73.9 58.35,74.15 60,74.15 61.65,74.15 45.35,74.2 67.92,74.375 69.804,74.401 71.604,74.401 73.404,74.401 45.35,74.7 67.92,74.875 59.175,74.975 60.825,74.975 45.35,75.5 58.35,75.8 60,75.8 61.65,75.8 64.78,75.875 45.35,76 59.175,76.625 60.825,76.625 45.35,76.8 45.35,77.3 58.35,77.45 60,77.45 61.65,77.45 67.55,78.325 67.55,78.825 67.575,79.975 67.575,80.475 68.65,80.575 69.15,80.575 69.95,80.575 70.45,80.575 71.25,80.575 71.75,80.575 72.55,80.575 73.05,80.575 56.35,80.823 56.35,81.323 55.275,83.123 55.776,83.123 50.95,85.623 51.451,85.623 52.25,85.623 52.751,85.623 53.55,85.623 54.051,85.623 67.2,86.575 67.7,86.575 68.475,86.575 68.975,86.575 69.75,86.575 70.25,86.575 71.025,86.575 71.525,86.575 55.324,87.425 55.825,87.425 56.326,87.425 57.174,87.425 57.675,87.425 58.176,87.425 59.024,87.425 59.525,87.425 60.026,87.425
  other v4: 112.55,68.625 121.275,69.825 115.825,70.975 112.55,72.31 112.6,74.99 114.175,74.975 119.75,76.4 119.75,77.725
  other v5: 102.785,81.2 119.175,85.325
HSE_IN: C90.2 U27.V3 X2.1 | length 13.2
  Top Layer w0.1: X2.1@76.623,61.551 76.772,61.7 C90.2@77.65,61.7 78.35,61.7 81.825,65.175 83.225,65.175 85.56,67.51 86.89,67.51 U27.V3@87.2,67.2
HSE_OUT: R75.2 U27.V2 | length 12.5
  Top Layer w0.1: R75.2@77.375,59.725 77.58,59.93 77.58,60.027 78.482,60.929 78.482,61.532 81.925,64.975 83.275,64.975 83.285,64.985 83.304,64.985 85.519,67.2 U27.V2@86.4,67.2
I2C7.SCL: R261.1 U26.33 U27.F16 | length 53.8
  Top Layer w0.09: v2@97.2,76.4 U27.F16@97.6,76.8
  Top Layer w0.15: U26.33@61,78.97 61,79.5 60.85,79.65 60.85,82.813 v3(61.262,83.225)
  Bottom Layer w0.1: v3@61.268,83.22 61.268,82.625 R261.1@61.305,82.588 ; v3@61.268,83.23 61.268,83.265 61.932,83.929 62.442,83.929 65.019,86.505 65.019,87.016 69.143,91.14 86.368,91.14 96.58,80.928 96.58,76.658 96.836,76.402 v2@97.197,76.402
  other v2: 97.2,76.4
I2C7.SDA: R260.1 U26.34 U27.G15 | length 56
  Top Layer w0.09: U27.G15@96.8,76 v2(97.2,75.6)
  Top Layer w0.15: U26.34@60.6,78.97 v3(60.6,83.225)
  Bottom Layer w0.1: R260.1@60.33,82.58 60.42,82.58 60.6,82.76 v3(60.6,83.225) ; v3@60.613,83.225 61.661,84.272 62.291,84.272 64.619,86.6 64.619,87.231 68.901,91.513 86.522,91.513 97.557,80.478 97.557,75.956 v2(97.2,75.6)
MP257_WAKEUP: U26.32 U27.Y2 | length 39.9
  Top Layer w0.09: v2(85.99,65.295) 86.042,65.295 86.348,65.6 U27.Y2@86.4,65.6
  Top Layer w0.15: v3(61.3,80.4) 61.3,79.653 61.4,79.553 U26.32@61.4,78.97
  Bottom Layer w0.1: v3(61.3,80.4) 61.881,80.4 62.3,80.819 62.3,81.657 63.418,82.775 74.895,82.775 78.295,79.375 78.295,71.723 82.182,67.835 83.45,67.835 v2(85.99,65.295)
NetB2_2: B2.2 C155.2 U26.1 | length 26.2
  Top Layer w0.15: B2.2@39.882,67.292 41.271,67.292 41.933,66.63 41.933,65.666 42.532,65.067 43.658,65.067 45.208,66.618 52.086,66.618 52.59,66.114 55.417,66.114 55.696,66.393 55.696,67.818 ; 55.7,67.825 55.847,67.972 56.054,67.972 C155.2@56.227,68.145 56.062,68.31 55.838,68.31 55.687,68.46 55.687,71.008 56.462,71.783 56.462,72.237 56.855,72.63 U26.1@57.4,72.63
NetC43_2: C43.2 U26.45 | length 6.7
  Top Layer w0.21: 56.275,77.6 U26.45@56.83,77.6
  Top Layer w0.25: C43.2@50.515,76.79 53.231,76.79 53.676,77.235 53.951,77.235 54.316,77.6 56.275,77.6
NetC61_2: C61.2 U27.M8 | length 1.1
  Top Layer w0.2: v2(90.8,72.4) U27.M8@91.2,72
  Bottom Layer w0.2: C61.2@90.317,72.288 90.391,72.362 90.762,72.362 v2(90.8,72.4)
NetC62_2: C62.2 R286.2 U27.T16 U27.Y16 | length 5.5
  Top Layer w0.1: U27.T16@97.6,68.8 97.6,68.425 97.1,67.925 97.1,66.1 U27.Y16@97.6,65.6 97.6,65.575 97.906,65.269 v2(97.906,65.243)
  Bottom Layer w0.2: C62.2@97.3,65.3 97.329,65.272 97.878,65.272 v2(97.906,65.243)
  Bottom Layer w0.3: R286.2@97.795,64.475 97.9,64.58 v2@97.9,65.238
NetC63_2: C63.2 C64.2 C65.2 R249.2 U27.V18 U27.V19 U27.Y19 | length 55.5
  Top Layer w0.2: U27.V18@99.2,67.2 v4@99.6,66.8 ; v2(99.6,65.2) U27.Y19@100,65.6 ; v4@99.6,66.8 U27.V19@100,67.2
  Top Layer w0.3: v2(72.351,61.252) 72.351,62.576 72.925,63.15 74.272,63.15 74.647,63.525 74.647,70.522 75.65,71.525 R249.2@75.65,74.55
  Signal Layer 2 w0.3: v2(72.351,61.252) 72.351,60.497 76.398,56.449 95.699,56.449 v2(100.025,60.775)
  Bottom Layer w0.3: v4@99.6,66.8 99.397,66.597 99.397,66.347 C65.2@99.375,66.325 99.4,66.3 99.4,66.05 99.475,65.975 99.475,65.7 C64.2@99.5,65.675 99.5,65.326 99.6,65.227 v2(99.6,65.2) 99.6,65.173 99.5,65.073 C63.2@99.5,64.675 99.5,63.761 100.003,63.259 100.003,60.797 v2(100.025,60.775)
  other v4: 99.6,66.825
NetC75_2: C75.2 C79.2 R267.1 U27.V7 | length 5.7
  Top Layer w0.2: v2(90,67.6) U27.V7@90.4,67.2
  Bottom Layer w0.15: R267.1@87.25,70.375 87.675,70.375 87.925,70.125 C79.2@88.238,70.125 ; C79.2@88.3,70.125 88.238,70.063 88.238,69.738 C75.2@87.925,69.425 88.5,68.85 89.317,68.85 89.602,68.565 89.602,68.038 90,67.641 v2(90,67.6)
NetC81_1: C81.1 R64.2 X1.1 | length 2.2
  Top Layer w0.1: X1.1@76.525,67.4 78.65,67.4 R64.2@78.7,67.45
NetC88_1: C88.1 CN12.2 | length 2.1
  Top Layer w0.3: C88.1@67.475,61.3 CN12.2@67.475,63.425
NetC88_2: C88.2 D6.2 R66.2 | length 8
  Top Layer w0.3: C88.2@67.475,60.4 67.475,59.726 67.651,59.55 68.675,59.55 ; R66.2@68.675,60.395 68.675,59.55 ; D6.2@70.625,63.075 70.625,60.025 70.15,59.55 68.675,59.55
NetC92_1: C92.1 R75.1 X2.3 | length 1.9
  Top Layer w0.09: X2.3@75.573,60.801 75.573,59.877 75.548,59.852 75.55,59.85 76.35,59.85 R75.1@76.475,59.725
NetC181_2: C181.2 C182.2 U24.C2 | length 3.5
  Top Layer w0.09: U24.C2@106.98,90.542 107.23,90.292 v1(107.23,89.492)
  Bottom Layer w0.25: v1@107.247,89.475 C181.2@108.6,89.475 ; v1@107.25,89.48 107.25,89.845 C182.2@107.685,90.28
NetC208_1: C208.1 U26.8 | length 5.4
  Top Layer w0.21: U26.8@60.2,72.63 60.2,71.134 60.625,70.709 60.625,70.345 60.798,70.173
  Top Layer w0.3: 60.798,70.173 61.3,69.67 61.3,68.843 61.175,68.718 C208.1@61.175,67.705
NetCN12_1: CN12.1 R66.1 | length 4.4
  Top Layer w0.3: CN12.1@67.475,64.675 68.344,64.675 68.675,64.344 R66.1@68.675,61.295
NetD5_1: D5.1 R248.1 U24.K5 | length 6.3
  Top Layer w0.2: v1(109.93,92.592) U24.K5@110.48,92.042
  Bottom Layer w0.2: v1@109.95,92.58 110.7,93.33 111.257,93.33 R248.1@111.782,93.855 111.782,96.913 D5.1@111.72,96.975
NetD6_1: D6.1 R67.1 | length 1.4
  Top Layer w0.3: D6.1@70.625,64.975 R67.1@70.625,66.375
NetL1_1: L1.1 U26.37 | length 4.2
  Top Layer w0.21: U26.37@59.4,78.97 59.4,79.525
  Top Layer w0.25: L1.1@59.2,83.135 59.2,80.173 59.4,79.973 59.4,79.525
NetL2_1: L2.1 U26.26 | length 4.1
  Top Layer w0.2: U26.26@63.417,77.6 63.9,77.6 64.225,77.925 64.225,80.56 ; L2.1@65.35,81.685 L2.1@65.35,82.2
NetL3_1: L3.1 U26.40 | length 5.9
  Top Layer w0.15: L3.1@53.198,80.162 L3.1@53.35,80.01
  Top Layer w0.21: L3.1@53.35,80.275 53.635,79.99 55.41,79.99 57.765,79.99 58.2,79.555 U26.40@58.2,78.97
NetL4_1: L4.1 U26.23 | length 3.8
  Top Layer w0.15: L4.1@66.86,75.885 L4.1@66.86,76.4
  Top Layer w0.21: U26.23@63.17,76.4 63.725,76.4
  Top Layer w0.25: 63.725,76.4 66.5,76.4
NetL5_1: L5.1 U26.48 | length 7.2
  Top Layer w0.15: L5.1@51.118,74.448 L5.1@51.37,74.7 ; L5.1@51.59,74.585 L5.1@51.59,75.1
  Top Layer w0.21: 56.275,76.4 U26.48@56.83,76.4
  Top Layer w0.25: 51.325,75.6 51.775,76.05 54.7,76.05 55.05,76.4 56.275,76.4 ; L5.1@51.59,75.1 51.59,75.615
NetL6_1: L6.1 U26.19 | length 4.9
  Top Layer w0.21: U26.19@63.17,74.8 63.725,74.8
  Top Layer w0.25: 63.725,74.8 64.123,74.8 64.298,74.625 64.65,74.625 64.875,74.4 64.875,73.325 65.571,72.629 65.925,72.629 65.93,72.624 L6.1@65.93,72.025
NetL7_1: L7.1 U26.51 | length 7.4
  Top Layer w0.21: 56.275,75.2 U26.51@56.83,75.2
  Top Layer w0.25: L7.1@53.925,70.425 L7.1@53.925,70.669 ; L7.1@53.975,69.95 54.375,70.35 54.375,72.184 54.85,72.659 54.85,74.503 55.547,75.2 56.275,75.2
NetLD11_1: LD11.1 R210.2 | length 1
  Top Layer w0.2: LD11.1@42.887,68.077 R210.2@42.887,69.07
NetR1_2: R1.2 U27.K16 | length 1.8
  Top Layer w0.09: U27.K16@97.6,73.6 U27.K16@97.657,73.6
  Top Layer w0.2: U27.K16@97.633,73.592 v4@97.962,73.263 ; U27.K16@97.657,73.6 v4@97.966,73.291
  Bottom Layer w0.09: R1.2@97.924,74.149 R1.2@97.978,74.096
  Bottom Layer w0.2: v4@97.978,73.3 R1.2@97.978,74.096
  other v4: 98.125,73.225
NetR2_2: R2.2 U26.56 | length 6.1
  Top Layer w0.15: R2.2@55.08,68.145 55.08,68.76 55.375,69.055 55.375,71.091 56.012,71.728 56.012,72.985 56.227,73.2 U26.56@56.755,73.2
NetR46_2: R46.2 U26.30 | length 2.8
  Top Layer w0.15: U26.30@62.2,78.97 62.2,80.87 62.532,81.202 62.532,81.43 R46.2@62.65,81.548
NetR57_2: R57.2 U26.12 | length 4.9
  Top Layer w0.21: U26.12@61.8,72.63 61.8,72.016 61.97,71.845
  Top Layer w0.3: 61.97,71.845 62.525,71.291 62.525,70.174 63.35,69.349 R57.2@63.35,68.4
NetR59_2: R59.2 U26.54 | length 8.5
  Top Layer w0.15: R59.2@52.98,68.145 52.98,68.64 53.15,68.81 54.236,68.81 54.875,69.449 54.875,71.298 55.512,71.935 55.512,73.335 56.177,74 U26.54@56.83,74
NetR60_2: R60.2 U26.55 | length 7.1
  Top Layer w0.15: R60.2@54.03,68.145 54.104,68.145 55.125,69.166 55.125,71.194 55.762,71.832 55.762,73.232 56.131,73.6 U26.55@56.83,73.6
NetR81_2: R81.2 U26.31 | length 5.7
  Top Layer w0.15: U26.31@61.8,78.97 61.8,80.973 61.95,81.123 61.95,83.81 62.038,83.898 R81.2@62.663,83.898
NetR163_1: R163.1 U2.A5 | length 1.1
  Top Layer w0.22: v4(117.3,66.9) U2.A5@117.75,66.9
  Bottom Layer w0.3: v4@117.3,66.925 117.675,66.925 R163.1@117.9,67.15
NetTP9_1: TP9.1 U24.H5 | length 1.7
  Top Layer w0.15: v2(109.48,91.642) U24.H5@109.48,92.042
  Bottom Layer w0.25: v2@109.5,91.63 109.5,91.131 TP9.1@110.091,90.54
NRST: C33.2 R81.1 U27.U3 | length 51
  Top Layer w0.09: 82.437,66.05 84.398,68.011 87.189,68.011 U27.U3@87.2,68
  Top Layer w0.1: v2@75.425,70.347 C33.2@75.425,69.775 75.4,69.775 75.195,69.57 75.195,69.544 74.971,69.32 74.971,64.793 75.534,64.23 79.62,64.23 81.44,66.05 82.437,66.05
  Top Layer w0.15: v2(62.651,85.672) 62.663,85.661 R81.1@62.663,84.798
  Bottom Layer w0.1: v2(62.651,85.672) 62.644,85.679 60.373,85.679 59.159,84.466 59.159,80.601 61.914,77.847 68.567,77.847 71.354,75.06 74.014,75.06 75.433,73.641 75.433,70.356 v2(75.424,70.347)
NRSTC1MS: D5.2 R27.1 R59.1 R272.1 U27.T3 | length 117.9
  Top Layer w0.09: v2(82.345,67.035) 82.859,67.035 84.03,68.206 86.216,68.206 86.49,68.48 86.88,68.48 U27.T3@87.2,68.8
  Top Layer w0.1: R59.1@52.98,67.245 52.988,67.237 v1@52.988,66.633 ; v2(72.425,66.05) 72.45,66.025 R27.1@73.125,66.025 ; v2(76.475,80.475) 79.028,83.028 v2@79.028,105.328
  Bottom Layer w0.1: R272.1@53.025,65.879 53.025,66.621 v1(52.983,66.663) 53.492,67.172 56.612,67.172 57.799,65.986 72.361,65.986 v2(72.425,66.05) 72.489,65.986 81.296,65.986 v2(82.345,67.035) 81.19,67.035 77.64,70.585 77.64,78.455 76.475,79.62 v2(76.475,80.475) ; v2@79.024,105.399 82.75,109.125 97.169,109.125 109.099,97.195 109.36,97.195 D5.2@109.58,96.975
  other v2: 79.033,105.377
OSC32_IN: C86.1 U27.R1 X1.2 | length 12.2
  Top Layer w0.09: C86.1@77.85,65.9 77.85,66.725 78,66.875 79.835,66.875 80,67.04 80,68.544 80.444,68.988 82.817,68.988 83.735,69.905 85.295,69.905 U27.R1@85.6,69.6
  Top Layer w0.1: X1.2@76.525,65.9 C86.1@77.85,65.9
OSC32_OUT: R64.1 U27.R2 | length 8.7
  Top Layer w0.09: R64.1@79.6,67.45 79.6,68.413 80.365,69.178 81.172,69.178 ; 81.172,69.175 82.75,69.175 83.66,70.085 85.532,70.085 86.017,69.6 U27.R2@86.4,69.6
PMIC_WAKEUPn: R46.1 U27.P6 | length 38.7
  Top Layer w0.09: v2(82.54,68.284) 82.555,68.298 83.068,68.298 83.983,69.212 85.187,69.212 85.289,69.315 87.318,69.315 87.332,69.315 87.495,69.478 87.495,69.492 87.705,69.702 87.705,69.722 87.878,69.895 87.898,69.895 87.899,69.896 87.899,69.9 88.371,69.9 88.546,70.075 89.275,70.075 U27.P6@89.6,70.4
  Top Layer w0.15: R46.1@62.65,82.448 v3(62.65,83.033)
  Bottom Layer w0.1: v3@62.703,83.022 75.078,83.022 78.559,79.541 78.559,72.368 82.444,68.482 82.444,68.461 82.54,68.365 v2(82.54,68.284)
PWR_CPU_ON: R60.1 R272.2 U27.T6 | length 42.5
  Top Layer w0.1: v1@54.014,66.64 54.014,67.229 R60.1@54.03,67.245 ; U27.T6@89.6,68.8 v2(90,68.4)
  Bottom Layer w0.1: R272.2@53.925,65.879 54.456,65.879 54.785,65.55 68.85,65.55 70.209,64.191 88.964,64.191 90.107,65.334 90.107,67.029 90.425,67.348 90.425,67.975 v2(90,68.4) ; R272.2@53.991,66.065 53.991,66.652 v1(54.009,66.67)
PWR_ON: R2.1 U27.T5 | length 39.8
  Top Layer w0.1: v1@55.08,66.64 R2.1@55.08,67.245 ; U27.T5@88.8,68.8 v2(89.2,68.4)
  Bottom Layer w0.1: v1(55.075,66.67) 55.119,66.67 56.017,65.772 69.502,65.772 70.717,64.558 75.903,64.558 76.287,64.942 88.706,64.942 89.615,65.85 89.615,67.702 89.206,68.111 89.206,68.394 v2(89.2,68.4)
VBAT: C87.2 D6.3 U27.P7 | length 24
  Top Layer w0.2: v2(90.019,69.225) 90.025,69.231 90.025,69.25 90.006,69.269 90.006,70.006 U27.P7@90.4,70.4
  Top Layer w0.3: D6.3@73.2,64.375 72.85,64.025 D6.3@72.825,64.025 73.188,64.388 73.825,65.025 C87.2@74.05,65.025 ; C87.2@73.925,65.125 74.17,65.125 74.175,65.13 v2(74.175,68.35)
  Signal Layer 2 w0.2: v2(74.175,68.35) 74.175,68.325 74.718,67.782 84.157,67.782 84.575,68.2 85.215,68.2 85.426,67.989 88.555,67.989 88.8,68.234 88.8,68.566 89.035,68.8 89.296,68.8 89.596,69.1 89.84,69.1 89.965,69.225 v2(90.019,69.225)
VDD1_DDR: C40.2 C51.2 C100.2 C101.2 C102.2 C103.2 C104.2 C131.2 U2.F1 U2.F12 U2.G4 U2.G9 U2.T4 U2.T9 U2.U1 U2.U12 U26.44 | length 157.8
  Top Layer w0.15: C102.2@110.875,70.125 111.1,70.35 111.95,70.35 U2.F12@112.15,70.15 112.166,70.165 112.366,70.165 112.675,70.475 113.981,70.475 114.307,70.801 114.568,70.801 114.571,70.804 114.886,70.804 115.216,70.475 116.05,70.475 116.325,70.75 ; 117.3,70.55 117.375,70.475 117.898,70.475 118.216,70.793 118.543,70.793 U2.G4@118.55,70.8 ; 118.85,76.975 120.618,76.975 120.62,76.973
  Top Layer w0.21: 56.275,78 U26.44@56.83,78
  Top Layer w0.22: C101.2@110.85,77.375 110.95,77.475 111.669,77.475 111.844,77.3 U2.U12@112.15,77.3 ; U2.T9@114.55,76.65 114.607,76.65 114.69,76.567 114.882,76.375 v4(114.95,76.375) ; 116.325,70.75 116.732,70.75 ; 117.3,70.55 117.1,70.75 116.732,70.75 ; U2.T4@118.55,76.675 118.85,76.975 ; 120.62,76.973 120.947,77.3 U2.U1@120.95,77.3 121.292,77.3 121.366,77.375 v4(121.45,77.375) 122.25,78.175 C104.2@122.275,78.175 ; U2.F1@120.95,70.15 121.85,71.05 C103.2@122.275,71.05 122.3,71.05 122.445,71.195 122.445,71.2 122.62,71.375 C51.2@123.275,71.375 ; C103.2@122.27,71.05 122.125,71.195 122.125,73.079 121.551,73.654 117.999,73.654 116.732,72.387 116.732,70.75
  Top Layer w0.25: v1(51.2,78.198) v1@51.202,78.196 ; v1@51.225,77.473 v1(51.202,77.473) 51.475,77.2 53.075,77.2 53.32,77.445 53.32,77.635 53.435,77.75 C40.2@53.505,77.75 ; C40.2@53.51,77.635 53.665,77.79 53.94,77.79 54.15,78 56.275,78
  Top Layer w0.3: C104.2@122.275,78.175 122.3,78.175 122.55,78.425 C100.2@123.3,78.425
  Top Layer w0.5: v1(51.202,77.473) v1@51.202,78.196
  Signal Layer 2 w0.6: v1@51.2,77.475 v1(51.2,78.198)
  Signal Layer 2 w0.7: v1(51.2,78.198) 49.244,78.198 48.209,77.163 46.837,77.163 45.883,78.117 45.883,85.733 51.699,91.549 91.801,91.549 92.714,90.636 96.269,90.636 105.136,81.769 119.27,81.769 122.1,78.938 122.1,77.375 122.1,74.3 v4(121.45,73.65) ; v4(121.45,77.375) 122.05,77.375 122.1,77.425
  Bottom Layer w0.3: v4@111.6,77.525 111.975,77.525 112.908,78.458 115.297,78.458 ; C131.2@114.75,76.975 114.83,76.975 114.83,77.03 114.88,77.08 114.935,77.08 115.297,77.442 115.297,78.458 ; C131.2@114.88,76.87 114.88,76.505 114.931,76.454 114.931,76.446 114.942,76.435 v4@114.95,76.435 ; v4@121.45,73.675 122.075,74.3 122.075,76.775 v4@121.45,77.4 ; v4(121.45,77.375) 119.975,78.85 118.014,78.85 117.622,78.458 115.297,78.458
  other v4: 111.6,77.5
VDD2_DDR: C41.2 C50.1 C53.2 C54.1 C55.2 C56.2 C57.2 C58.2 C59.2 C60.2 C105.2 C106.1 C107.1 C108.1 C123.2 C124.1 C125.1 C130.1 C151.1 C175.1 C176.2 C200.2 C202.2 L5.2 LNK8.2 R163.2 U2.A4 U2.A9 U2.AA3 U2.AA5 U2.AA8 U2.AA10 U2.AB4 U2.AB9 U2.B3 U2.B5 U2.B8 U2.B10 U2.D1 U2.D5 U2.D8 U2.D12 U2.F3 U2.F5 U2.F8 U2.F10 U2.G2 U2.H1 U2.H5 U2.H8 U2.H12 U2.K1 U2.K3 U2.K10 U2.K12 U2.N1 U2.N3 U2.N10 U2.N12 U2.R1 U2.R5 U2.R8 U2.R12 U2.T2 U2.U3 U2.U5 U2.U8 U2.U10 U2.W1 U2.W5 U2.W8 U2.W12 U27.K15 U27.L14 U27.L16 U27.M15 U27.N14 U27.P15 U27.R14 U27.R16 | length 71.9
  Top Layer w0.09: v4(113.35,79) 113.413,78.938 113.905,78.938 114.045,78.797 114.045,77.595 U2.U10@113.75,77.3 ; v4(118.375,66.25) 118.397,66.271 118.397,66.524 118.515,66.642 118.515,66.865 U2.A4@118.55,66.9 ; v4(119.35,65.95) 119.695,66.295 119.695,66.593 119.645,66.643 119.645,67.255 U2.B3@119.35,67.55 ; U2.K3@119.35,72.775 U2.K3@119.35,72.788 ; U2.K1@120.95,72.825 U2.K1@120.975,72.825
  Top Layer w0.1: U27.R16@97.575,69.6 U27.R16@97.6,69.6
  Top Layer w0.15: v1(47.798,78.165) 48.2,77.763 LNK8.2@48.2,77.723 ; U2.F10@113.75,70.15 113.76,70.16 114.035,70.16 114.35,70.475 114.732,70.475 115.032,70.175 U2.F8@115.35,70.175 ; 114.095,79.575 114.75,79.575 115.075,79.9 U2.AA8@115.35,79.9 ; U2.F8@115.35,70.15 U2.F8@115.367,70.166 ; U2.F5@117.75,70.15 118.025,70.15 118.35,70.475 118.685,70.475 118.712,70.502 118.903,70.502 118.95,70.55 ; 118.95,70.525 118.975,70.525 119.325,70.175 U2.F3@119.375,70.175
  Top Layer w0.2: v2@95.6,73.15 v2(95.625,73.15) 95.65,73.15 U27.L14@96,72.8 v2(96.42,72.379) ; v2@95.625,71.575 U27.N14@96,71.2 U27.M15@96.8,72 v2@96.421,72.379 ; v2@96.4,74 U27.K15@96.8,73.6 v2(97.15,73.25) ; v2(96.525,70) 96.563,70.038 96.563,70.163 U27.P15@96.8,70.4 97.05,70.65 v2(97.05,70.8) ; v2(97.05,69.2) 97.2,69.2 U27.R16@97.6,69.6 ; v2@97.125,73.275 v2(97.15,73.25) ; U27.L16@97.6,72.8 v2(97.15,73.25)
  Top Layer w0.22: C50.1@110.85,72.65 111.46,72.65 111.735,72.375 v4@111.75,72.375 ; C105.2@110.85,74.875 111.502,74.875 111.651,75.024 ; v4(111.6,79.05) 111.635,79.016 111.735,79.016 U2.W12@112.15,78.6 ; v4(111.75,68.625) 111.785,68.659 111.938,68.659 112.129,68.85 U2.D12@112.15,68.85 ; U2.H12@112.15,71.45 111.755,71.845 111.755,72.37 v4@111.75,72.375 ; U2.K12@112.15,72.75 112.138,72.75 111.763,72.375 v4@111.75,72.375 ; U2.N12@112.15,74.7 112.135,74.715 111.96,74.715 111.651,75.024 ; U2.R12@112.15,76 112.15,75.988 111.65,75.488 111.65,75.475 111.651,75.474 111.651,75.024 ; v4(113.35,72.375) 113.363,72.375 113.738,72.75 U2.K10@113.75,72.75 ; v4(113.35,79) 113.38,79.03 113.38,79.53 U2.AA10@113.75,79.9 U2.AA10@113.77,79.9 ; v4(113.375,69.75) 113.75,70.125 U2.F10@113.75,70.15 ; U2.B10@113.75,67.55 113.763,67.55 114.138,67.175 v4(114.15,67.175) 114.185,67.141 114.288,67.141 114.529,66.9 U2.A9@114.55,66.9 ; U2.N10@113.75,74.7 113.772,74.7 113.953,74.519 114.116,74.519 v4@114.15,74.485 ; 114.095,79.575 U2.AA10@113.77,79.9 ; U2.AB9@114.55,80.55 114.538,80.55 114.188,80.2 114.175,80.2 114.141,80.166 114.038,80.166 113.772,79.9 U2.AA10@113.77,79.9 ; U2.B8@115.35,67.55 v4(115.675,67.875) 115.675,67.924 115.71,67.959 115.71,68.49 U2.D8@115.35,68.85 ; U2.F8@115.35,70.175 115.363,70.163 116.413,70.163 116.425,70.175 116.438,70.163 117.738,70.163 U2.F5@117.75,70.15 ; U2.H8@115.35,71.45 115.363,71.438 116.088,71.438 v4(116.1,71.425) ; U2.R8@115.35,76 115.372,76 115.697,75.675 v4(115.725,75.675) ; U2.U8@115.35,77.3 115.366,77.285 115.717,77.285 115.752,77.25 v4(115.8,77.25) ; U2.W8@115.35,78.6 v4(115.675,78.925) ; v4(117.25,80.05) 117.299,80.05 117.434,79.915 117.735,79.915 U2.AA5@117.75,79.9 ; v4(117.375,78.95) 117.388,78.95 117.738,78.6 U2.W5@117.75,78.6 ; v4(117.4,75.675) U2.R5@117.713,75.988 ; v4(117.4,77) 117.425,77 U2.U5@117.741,77.315 ; U2.B5@117.75,67.55 v4(117.35,67.95) 117.38,67.98 117.38,68.48 U2.D5@117.75,68.85 ; U2.H5@117.75,71.45 117.772,71.45 118.038,71.716 118.116,71.716 v4@118.15,71.75 ; U2.AB4@118.55,80.55 118.572,80.55 118.863,80.259 118.916,80.259 v4(118.95,80.225) 118.985,80.191 119.038,80.191 119.329,79.9 U2.AA3@119.35,79.9 ; v4(118.95,69.925) 118.985,69.959 119.138,69.959 119.329,70.15 U2.F3@119.35,70.15 ; v4(118.95,73.2) 118.95,73.172 119.35,72.772 U2.K3@119.35,72.75 ; v4(118.95,74.425) 118.985,74.459 119.11,74.459 U2.N3@119.35,74.7 ; v4(118.95,77.725) 118.95,77.713 119.35,77.313 U2.U3@119.35,77.3 ; U2.T2@120.123,76.655 120.145,76.655 U2.T2@120.15,76.65 120.425,76.375 120.575,76.375 U2.R1@120.95,76 121.241,75.709 121.316,75.709 v4(121.35,75.675) ; U2.G2@120.15,70.8 120.172,70.8 120.463,71.091 120.541,71.091 v4(120.575,71.125) ; U2.D1@120.95,68.85 v4(121.275,69.175) C106.1@122.25,69.175 ; U2.H1@120.95,71.45 v4(121.4,71.45) ; U2.K1@120.95,72.763 U2.K1@120.95,72.75 v4(121.4,72.75) ; U2.N1@120.95,74.7 121.241,74.991 121.316,74.991 v4(121.35,75.025) ; U2.W1@120.95,78.6 120.963,78.6 121.263,78.3 v4@121.275,78.3
  Top Layer w0.3: U27.R14@96,69.6 96.125,69.6 v2(96.525,70) ; v4(121.35,75.025) v4@121.35,75.495 ; v4(121.35,75.675) v4@121.35,75.495 ; C107.1@122.275,75.6 122.17,75.495 v4@121.35,75.495
  Top Layer w0.64: C202.2@47.475,74.45 C41.2@47.475,75.75 C200.2@47.475,77.05 ; 47.475,77.495 47.475,77.925
  Top Layer w0.8: C202.2@47.7,74.45 L5.2@49.475,74.45
  Signal Layer 2 w0.3: v2@96.356,72.394 96.406,72.394 v2@96.425,72.375
  Bottom Layer w0.2: v2@96.4,74 96.4,73.946 96.549,73.796 96.549,73.599 C60.2@96.624,73.524 ; C60.2@96.631,73.524 96.704,73.452 96.933,73.452 97.135,73.25 v2(97.15,73.25) ; v2@97.125,73.275 v2(97.15,73.25) ; v2@97.15,73.23 v2(97.15,73.25)
  Bottom Layer w0.22: v4(114.125,80.25) 114.125,80.825 114.202,80.901 114.202,81.926 C123.2@114.4,82.125 ; v4@114.125,80.275 114.125,80.85 C125.1@114.175,80.9 114.202,80.926 114.202,81.951 C123.2@114.4,82.15 ; v4@115.8,77.275 116.022,77.054 116.397,77.054 C130.1@116.4,77.05 ; v4(117.25,80.05) 118.275,80.05 C124.1@118.3,80.075 118.441,80.216 118.916,80.216 v4@118.95,80.25 ; v4@117.35,67.975 117.675,67.975 R163.2@117.9,67.75 ; v4@119.35,65.975 119.399,65.975 119.554,65.82 119.88,65.82 C108.1@120.025,65.675 120.05,65.675 120.3,65.425 C176.2@121.125,65.425 ; v4@121.4,72.775 121.435,72.809 122.01,72.809 C151.1@122.05,72.85
  Bottom Layer w0.275: C175.1@113.55,67.05 113.7,67.2 v4@114.15,67.2
  Bottom Layer w0.3: v2@95.6,71.575 95.9,71.275 C55.2@96.1,71.275 ; v2@95.6,73.15 v2(95.625,73.15) ; v2@95.627,73.15 v2(95.625,73.15) ; C59.2@96.1,69.725 96.175,69.8 96.308,69.8 96.508,70 v2(96.525,70) ; v2(96.42,72.379) 96.394,72.379 96.124,72.649 96.124,72.687 96.099,72.712 96.099,72.85 C56.2@96.074,72.875 96.049,72.9 95.875,72.9 v2(95.625,73.15) ; v2@96.425,72.375 96.425,72.347 96.549,72.223 96.549,71.999 C57.2@96.574,71.974 ; v2@97.023,70.8 v2(97.05,70.8) 97.077,70.8 97.227,70.65 97.45,70.65 C54.1@97.475,70.625 ; v2(97.05,69.2) 97.069,69.219 97.269,69.219 C53.2@97.45,69.4 ; v2@97.125,73.275 97.425,73.275 C58.2@97.5,73.2
  other v1: 47.123,78.165 47.123,78.89 47.798,78.89
  other v2: 95.65,71.55 96.425,74
  other v4: 116.5,70.225 118.15,71.7 111.75,72.325 114.15,74.475 111.65,75.525 121.275,78.275
VDD3V3_USB: C156.2 R286.1 U26.13 | length 47
  Top Layer w0.21: U26.13@62.2,72.63 62.2,72.2 62.663,71.737 62.918,71.737 62.92,71.735 62.99,71.735 63.125,71.6 C156.2@63.125,71.53
  Top Layer w0.3: C156.2@63.125,71.53 v3(63.735,71.53)
  Signal Layer 2 w0.5: v3(63.735,71.53) 66.62,71.53 68.65,69.5 68.65,65.93 77.411,57.17 91.295,57.17 97.19,63.065 v2(97.19,63.078)
  Bottom Layer w0.5: v2(97.19,63.078) 97.687,63.575 R286.1@97.725,63.575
